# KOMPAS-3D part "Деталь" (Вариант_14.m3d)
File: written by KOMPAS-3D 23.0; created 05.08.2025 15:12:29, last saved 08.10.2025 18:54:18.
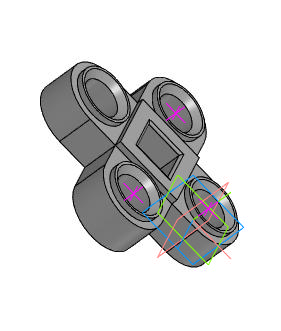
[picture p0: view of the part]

Document properties: Автор: Admin; Полное имя файла: C:\Users\ssafo\OneDrive\Desktop\ЦД_Грант\Решенные варианты\Вариант_14.m3d

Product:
- Part/product: Деталь
    Масса: 2.705927
    Форматы листов документа: A4

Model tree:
1. Эскиз:1
2. Элемент выдавливания:1
     Расстояние 1 = 15; Расстояние 2 = 15
3. Эскиз:2  (with: Элемент выдавливания:1)
4. Элемент выдавливания:2
     Расстояние 1 = 5
5. Эскиз:3  (with: Элемент выдавливания:2)
6. Элемент выдавливания:3
     Расстояние 2 = 28
7. Фаска:1  (with: Элемент выдавливания:3)
     Угол = 45; Длина 1 = 5; Длина 2 = 5
8. Эскиз:4  (with: Элемент выдавливания:1)
9. Массив по точкам:1
10. Экземпляр ( 3 )  (with: Элемент выдавливания:3, Фаска:1, Элемент выдавливания:2)
11. Экземпляр ( 2 )  (with: Элемент выдавливания:3, Фаска:1, Элемент выдавливания:2)
12. Экземпляр ( 1 )  (with: Элемент выдавливания:3, Фаска:1, Элемент выдавливания:2)
13. Эскиз:5  (with: Элемент выдавливания:1)
14. Элемент выдавливания:4
     Расстояние 1 = 5
15. Эскиз:6  (with: Элемент выдавливания:4)
16. Элемент выдавливания:5
     Расстояние 2 = 30
17. Скругление:1  (with: Элемент выдавливания:5)
     Радиус = 2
